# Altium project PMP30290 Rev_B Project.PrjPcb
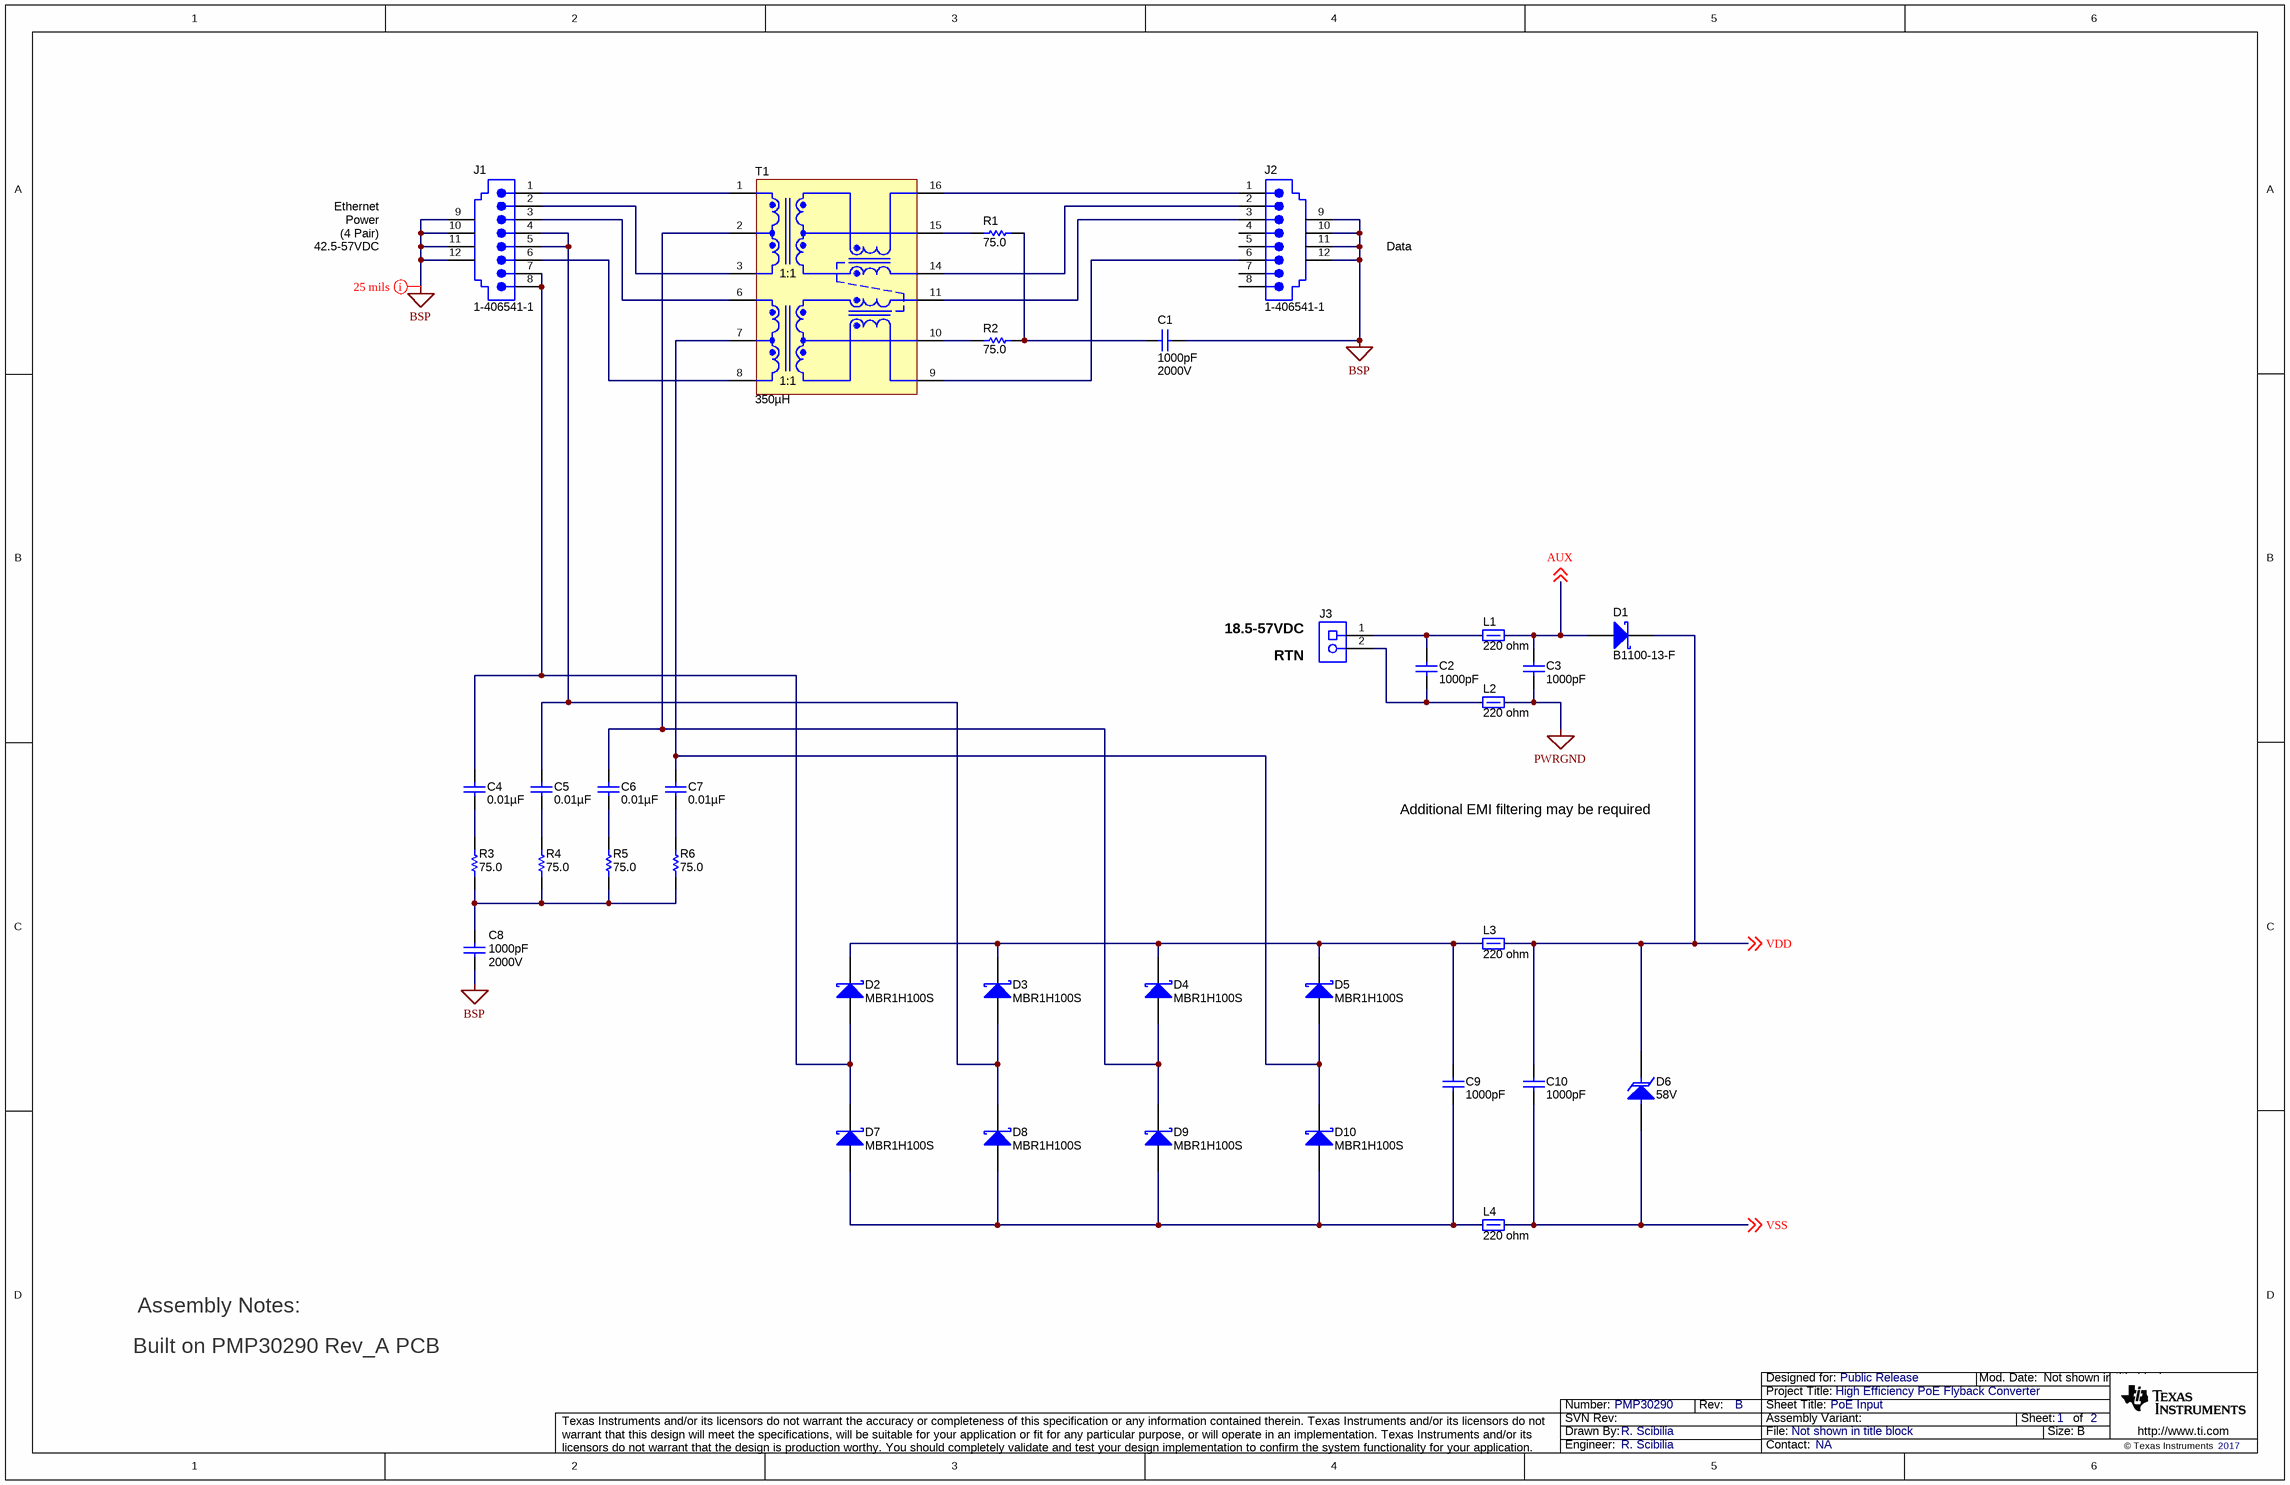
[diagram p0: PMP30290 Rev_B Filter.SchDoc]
CopyrightYear: 2017; PCB_Layout: R. Scibilia; PCB_Rev: A; PRJ_Customer: Public Release; PRJ_Engineer: R. Scibilia; PRJ_Number: PMP30290; PRJ_Title: High Efficiency PoE Flyback Converter; SCH_Rev: B; TechSupport: NA
2 sheets, 95 parts. Net scope: global (net labels, ports and power ports of the same name join across sheets).
Board file: PMP30290 Rev_A PCB.PcbDoc
Sheets:
  PMP30290 Rev_B Filter.SchDoc
  PMP30290 Rev_B Power Stage.SchDoc

## Sheet PMP30290 Rev_B Filter.SchDoc: PoE Input
size 431 x 279 mm; Date: Not shown in title block; ApprovedBy: Not shown in title block; CheckedBy: Not shown in title block; Author: Not shown in title block; CompanyName: Not shown in title block; DrawnBy: R. Scibilia; Engineer: Not shown in title block; Organization: Not shown in title block; Address1: Not shown in title block; Address2: Not shown in title block; Address3: Not shown in title block; Address4: Not shown in title block; DocumentNumber: 1; Revision: Use project parameter SCH_Rev; SheetNumber: 1; SheetTotal: 2; PageSetup: Record=PageOptions¦CenterHorizontal=True¦CenterVertical=True¦PrintScale=1.00¦XCorrection=1.00¦YCorrection=1.00¦PrintKind=0¦BorderSize=5000000¦LeftOffset=0¦BottomOffset=0¦Orientation=2¦PaperLength=1000¦PaperWidth=1000¦Scale=100¦PaperSource=15¦PrintQuality=600¦MediaType=1¦DitherType=10¦PaperKind=Letter¦PrintScaleMode=1

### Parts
C1  ValueDisplayed: 1000pF  Value2: 2000V  [1812_254]  (hidden comment: 1812GC102KA1)
C2  ValueDisplayed: 1000pF  [0603]  (hidden comment: C1608X7R2A102K080AA)
C3  ValueDisplayed: 1000pF  [0603]  (hidden comment: C1608X7R2A102K080AA)
C4  ValueDisplayed: 0.01µF  [0603]  (hidden comment: C0603C103K1RACTU)
C5  ValueDisplayed: 0.01µF  [0603]  (hidden comment: C0603C103K1RACTU)
C6  ValueDisplayed: 0.01µF  [0603]  (hidden comment: C0603C103K1RACTU)
C7  ValueDisplayed: 0.01µF  [0603]  (hidden comment: C0603C103K1RACTU)
C8  ValueDisplayed: 1000pF  Value2: 2000V  [1812_254]  (hidden comment: 1812GC102KA1)
C9  ValueDisplayed: 1000pF  [0603]  (hidden comment: C1608X7R2A102K080AA)
C10  ValueDisplayed: 1000pF  [0603]  (hidden comment: C1608X7R2A102K080AA)
D1  B1100-13-F  [SMA]
D2  value MBR1H100S  [SOD-123FL]  (hidden comment: MBR1H100SFT3G)
D3  value MBR1H100S  [SOD-123FL]  (hidden comment: MBR1H100SFT3G)
D4  value MBR1H100S  [SOD-123FL]  (hidden comment: MBR1H100SFT3G)
D5  value MBR1H100S  [SOD-123FL]  (hidden comment: MBR1H100SFT3G)
D6  value 58V  [SMA]  (hidden comment: SMAJ58A-13-F)
D7  value MBR1H100S  [SOD-123FL]  (hidden comment: MBR1H100SFT3G)
D8  value MBR1H100S  [SOD-123FL]  (hidden comment: MBR1H100SFT3G)
D9  value MBR1H100S  [SOD-123FL]  (hidden comment: MBR1H100SFT3G)
D10  value MBR1H100S  [SOD-123FL]  (hidden comment: MBR1H100SFT3G)
J1  1-406541-1  [TEC_1-406541-1]
J2  1-406541-1  [TEC_1-406541-1]
J3  ED555/2DS  [TERM_BLK_ED555-2DS]  (value not drawn)
L1  value 220 ohm  [0603]  (hidden comment: MPZ1608S221A)
L2  value 220 ohm  [0603]  (hidden comment: MPZ1608S221A)
L3  value 220 ohm  [0603]  (hidden comment: MPZ1608S221A)
L4  value 220 ohm  [0603]  (hidden comment: MPZ1608S221A)
R1  ValueDisplayed: 75.0  [0603L]  (hidden comment: CRCW060375R0FKEA)
R2  ValueDisplayed: 75.0  [0603L]  (hidden comment: CRCW060375R0FKEA)
R3  ValueDisplayed: 75.0  [0603L]  (hidden comment: CRCW060375R0FKEA)
R4  ValueDisplayed: 75.0  [0603L]  (hidden comment: CRCW060375R0FKEA)
R5  ValueDisplayed: 75.0  [0603L]  (hidden comment: CRCW060375R0FKEA)
R6  ValueDisplayed: 75.0  [0603L]  (hidden comment: CRCW060375R0FKEA)
T1  ValueDisplayed: 350µH  [PULSE_H2019FNL]  (hidden comment: H2019FNLT)

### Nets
BSP: C1.2 C8.2 J1.9 J1.10 J1.11 J1.12 J2.9 J2.10 J2.11 J2.12
PWRGND: C3.2 L2.2
AUX: C3.1 D1.2(A) L1.2 ; off-sheet AUX
VDD: C10.1 D1.1(K) D6.1(K) L3.2 ; off-sheet VDD
VSS: C10.2 D6.2(A) L4.2 ; off-sheet VSS
NetC1_1: C1.1 R1.1 R2.1
NetC2_1: C2.1 J3.1 L1.1
NetC2_2: C2.2 J3.2 L2.1
NetC4_1: C4.1 D2.2(A) D7.1(K) J1.7 J1.8
NetC4_2: C4.2 R3.2
NetC5_1: C5.1 D3.2(A) D8.1(K) J1.4 J1.5
NetC5_2: C5.2 R4.2
NetC6_1: C6.1 D4.2(A) D9.1(K) T1.2(TCT)
NetC6_2: C6.2 R5.2
NetC7_1: C7.1 D5.2(A) D10.1(K) T1.7(RCT)
NetC7_2: C7.2 R6.2
NetC8_1: C8.1 R3.1 R4.1 R5.1 R6.1
NetC9_1: C9.1 D2.1(K) D3.1(K) D4.1(K) D5.1(K) L3.1
NetC9_2: C9.2 D7.2(A) D8.2(A) D9.2(A) D10.2(A) L4.1
NetJ1_1: J1.1 T1.1(TD+)
NetJ1_2: J1.2 T1.3(TD-)
NetJ1_3: J1.3 T1.6(RD+)
NetJ1_6: J1.6 T1.8(RD-)
NetJ2_1: J2.1 T1.16(TX+)
NetJ2_2: J2.2 T1.14(TX-)
NetJ2_3: J2.3 T1.11(RX+)
NetJ2_6: J2.6 T1.9(RX-)
NetR1_2: R1.2 T1.15(TXCT)
NetR2_2: R2.2 T1.10(RXCT)

Not connected (* = marked no-connect by the designer): J2 4 5 7 8

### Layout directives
rule Clearance Constraint [Clearance = 20mil]: BSP

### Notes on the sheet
- Power
- Ethernet
- (4 Pair)
- 42.5-57VDC
- Data
- (near J3) 18.5-57VDC
- (near J3) RTN
- Additional EMI filtering may be required
- Assembly Notes:
- Built on PMP30290 Rev_A PCB

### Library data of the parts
C1 C8 = 1812GC102KA1: CAP, CERM, 1000 pF, 2000 V, +/- 10%, X7R, 1812; Manufacturer: AVX; Polarized: N; CompType: Capacitor; Value: 1000pF; U/M: EA; Cap_F: 0.000000001; Tolerance_%: 10; Value1: Unknown; VDC_V: 2000; TaMin_C: -55; TaMax_C: 125; Cap_Case: 1812; SizeArea_mm2: 14.4; SizeAreaWB_mm2: 23.1; SizeX_mm: 4.5; SizeY_mm: 3.2; SizeZ_mm: 2.54; AEC Category: Q200
C2 C3 C9 C10 = C1608X7R2A102K080AA: CAP, CERM, 1000 pF, 100 V, +/- 10%, X7R, 0603; Manufacturer: TDK; Polarized: N; CompType: Capacitor; Value: 1000pF; U/M: EA; Cap_F: 0.000000001; Tolerance_%: 10; Value1: Unknown; VDC_V: 100; Value2: 100V; TaMin_C: -55; TaMax_C: 125; SizeArea_mm2: 1.28; SizeAreaWB_mm2: 4.68; SizeX_mm: 1.6; SizeY_mm: 0.8; SizeZ_mm: 1; AEC Category: Q200; Green_Lifecycle: Active; Green_REACh: Passed
C4-C7 = C0603C103K1RACTU: CAP, CERM, 0.01 µF, 100 V, +/- 10%, X7R, 0603; Manufacturer: Kemet; Polarized: N; CompType: Capacitor; Value: 0.01uF; U/M: EA; Cap_F: 0.00000001; Tolerance_%: 10; Value1: Unknown; VDC_V: 100; Value2: 100V; TaMin_C: -55; TaMax_C: 125; SizeArea_mm2: 1.28; SizeAreaWB_mm2: 4.68; SizeX_mm: 1.6; SizeY_mm: 0.8; SizeZ_mm: 1; AEC Category: Q200; Green_Lifecycle: Active; Green_REACh: Passed
D1 = B1100-13-F: Diode, Schottky, 100 V, 1 A, SMA; Manufacturer: Diodes Inc.; Value: 100V; U/M: EA; Vf_V: 0.79; Value1: 1A; Value2: 0.79V; Io_A: 1; Vr_V: 100; TJmax_C: 150; RJC_CperW: 25; SizeAreaWB_mm2: 37.3428; SizeArea_mm2: 16.3228; SizeX_mm: 5.59; SizeY_mm: 2.92; SizeZ_mm: 2.87; AEC Category: Q101
D2-D5 D7-D10 = MBR1H100SFT3G: Diode, Schottky, 100 V, 1 A, SOD-123FL; Manufacturer: ON Semiconductor; U/M: EA; Vf_V: 0.76; Value1: 1A; Value2: 0.76V; Io_A: 1; Vr_V: 100; TJmax_C: 175; RJC_CperW: 85; SizeAreaWB_mm2: 12.19; SizeArea_mm2: 5.94; SizeX_mm: 3.6; SizeY_mm: 1.65; SizeZ_mm: 0.98; AEC Category: Q101; Green_Lifecycle: Active; Green_REACh: Passed
D6 = SMAJ58A-13-F: Diode, TVS, Uni, 58 V, SMA; Manufacturer: Diodes Inc.; U/M: EA; Power_W: 1; Vr_V: 58; Value1: 1W; SizeAreaWB_mm2: 37.3428; SizeArea_mm2: 16.3228; SizeX_mm: 5.59; SizeY_mm: 2.92; SizeZ_mm: 2.87; AEC Category: Q101
J1 J2 = 1-406541-1: RJ-45, Right Angle, No LED, tab up; Manufacturer: AMP; SymbolCreator: x0208326; Note: updated F/S per request.  Made footprint to max size.  2103-11-27; CompType: Connector; U/M: EA
J3 = ED555/2DS: Terminal Block, 3.5mm Pitch, 2x1, TH; Manufacturer: On-Shore Technology; SymbolCreator: a0412235; Pitch_mm: 3.5; Gender: Female; Shrouded: N; Row_Count: 1; ContactFinish: Brass; Current_A: 6; Voltage_V: 150; Cert_CULUS: Y; Green_Lifecycle: Active; Green_REACh: Passed
L1-L4 = MPZ1608S221A: Ferrite Bead, 220 ohm @ 100 MHz, 2.2 A, 0603; Manufacturer: TDK; Imax_A: 2.2; DCR_ohm: 0.05; Value1: 0.05 ohm; Value2: 2.2A; ZTyp@100MHz_Ohm: 220
R1-R6 = CRCW060375R0FKEA: RES, 75.0, 1%, 0.1 W, 0603; Manufacturer: Vishay-Dale; CompType: Resistor; Value: 75.0; Res_ohm: 75; Value_Code: 75R0; Tolerance_%: 1; Power_W: 0.1; Value2: 0.1W; TempCo: 100 ppm/C; EIA_Code: E96; U/M: EA; SizeArea_mm2: 1.28; SizeX_mm: 1.6; SizeY_mm: 0.8; AEC Category: Q200
T1 = H2019FNLT: Transformer, 350uH, SMT; Manufacturer: Pulse Engineering; SymbolCreator: x0208325; DCR_ohm: 0.65; Lp: 350; Ind_H: 0.00035; Green_Lifecycle: Not Set; Green_REACh: Incomplete

## Sheet PMP30290 Rev_B Power Stage.SchDoc: Flyback Converter
size 431 x 279 mm; Date: Not shown in title block; ApprovedBy: Not shown in title block; CheckedBy: Not shown in title block; Author: Not shown in title block; CompanyName: Not shown in title block; DrawnBy: R. Scibilia; Engineer: Not shown in title block; Organization: Not shown in title block; Address1: Not shown in title block; Address2: Not shown in title block; Address3: Not shown in title block; Address4: Not shown in title block; DocumentNumber: 2; Revision: Use project parameter SCH_Rev; SheetNumber: 2; SheetTotal: 2; PageSetup: Record=PageOptions¦CenterHorizontal=True¦CenterVertical=True¦PrintScale=0.66¦XCorrection=1.00¦YCorrection=1.00¦PrintKind=0¦BorderSize=5000000¦LeftOffset=0¦BottomOffset=0¦Orientation=2¦PaperLength=1000¦PaperWidth=1000¦Scale=100¦PaperSource=15¦PrintQuality=600¦MediaType=1¦DitherType=10¦PaperKind=Letter¦PrintScaleMode=1
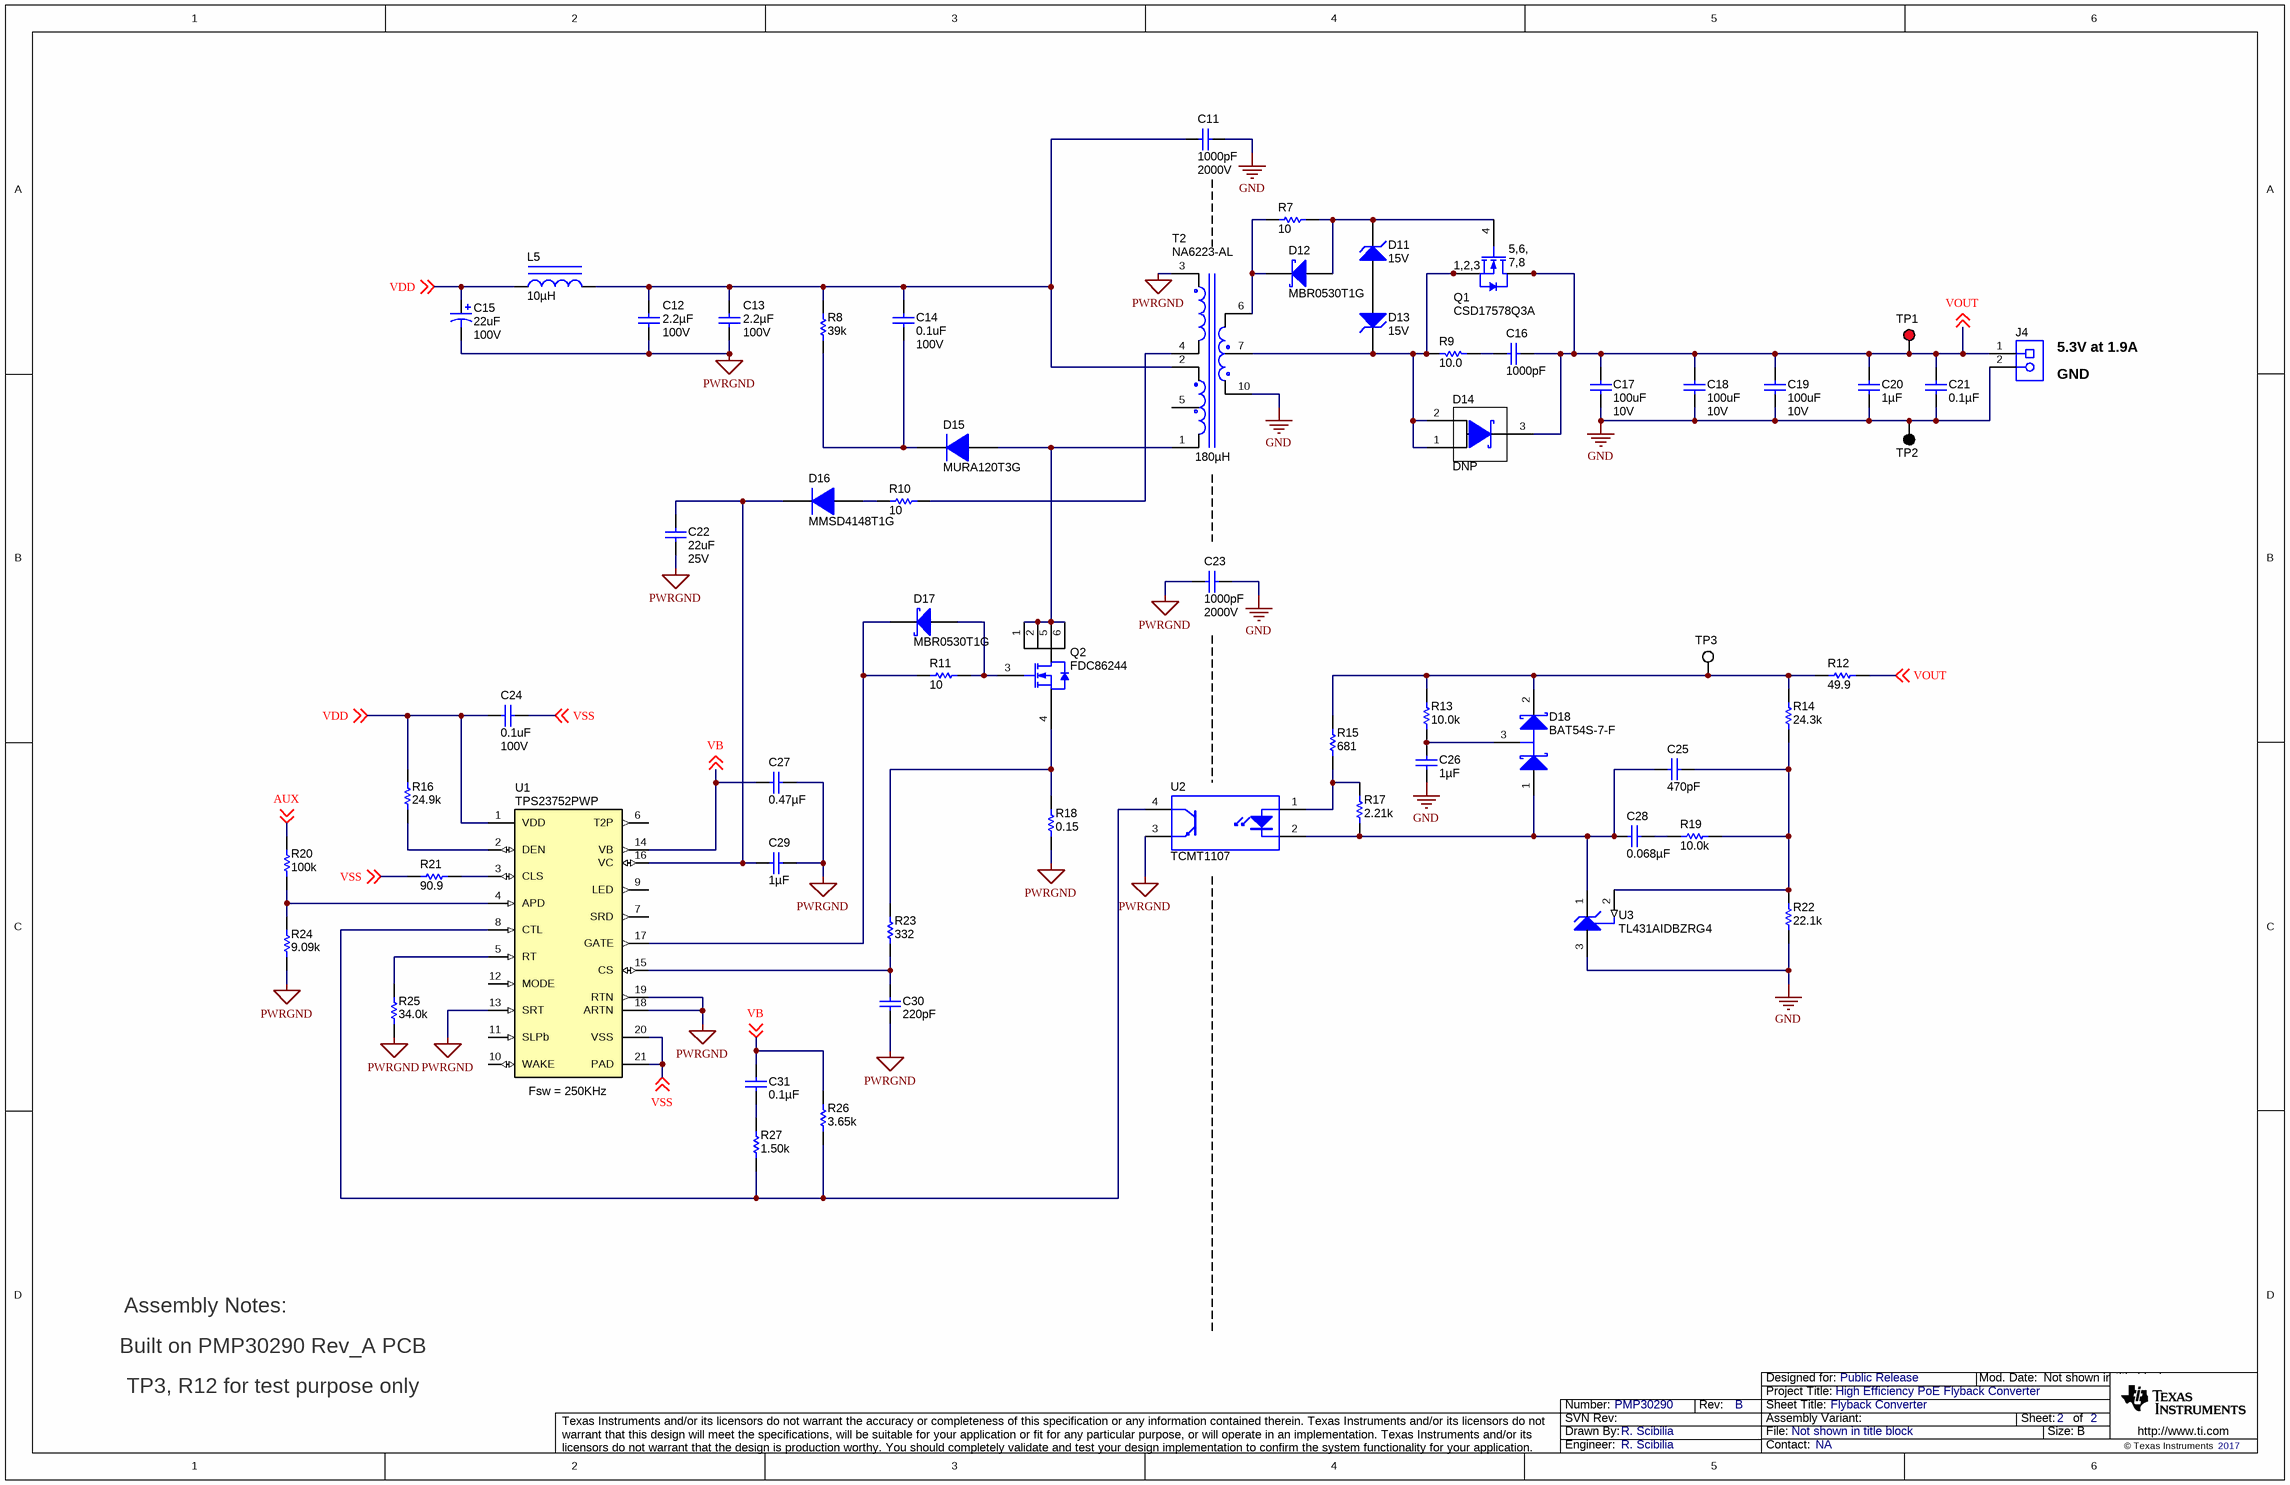
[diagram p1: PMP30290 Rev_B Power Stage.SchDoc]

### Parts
C11  ValueDisplayed: 1000pF  Value2: 2000V  [1812_254]  (hidden comment: 1812GC102KA1)
C12  ValueDisplayed: 2.2µF  Value2: 100V  [1210_270L]  (hidden comment: GRM32ER72A225KA35L)
C13  ValueDisplayed: 2.2µF  Value2: 100V  [1210_270L]  (hidden comment: GRM32ER72A225KA35L)
C14  value 0.1uF  Value2: 100V  [0805_HV]  (hidden comment: C2012X7R2A104K125AA)
C15  value 22uF  Value2: 100V  [CAPSMT_62_JA0]  (hidden comment: EMVH101ADA220MJA0G)
C16  ValueDisplayed: 1000pF  [0603]  (hidden comment: C1608X7R2A102K080AA)
C17  value 100uF  Value2: 10V  [1210_280]  (hidden comment: C1210C107M8PACTU)
C18  value 100uF  Value2: 10V  [1210_280]  (hidden comment: C1210C107M8PACTU)
C19  value 100uF  Value2: 10V  [1210_280]  (hidden comment: C1210C107M8PACTU)
C20  ValueDisplayed: 1µF  [0603]  (hidden comment: 885012206052)
C21  ValueDisplayed: 0.1µF  [0603]  (hidden comment: 885012206046)
C22  value 22uF  Value2: 25V  [1210_280]  (hidden comment: 12103D226MAT2A)
C23  ValueDisplayed: 1000pF  Value2: 2000V  [1812_254]  (hidden comment: 1812GC102KA1)
C24  value 0.1uF  Value2: 100V  [0805_HV]  (hidden comment: C2012X7R2A104K125AA)
C25  ValueDisplayed: 470pF  [0603]  (hidden comment: GRM1885C1H471JA01D)
C26  ValueDisplayed: 1µF  [0603]  (hidden comment: 885012206052)
C27  ValueDisplayed: 0.47µF  [0603]  (hidden comment: GRM188R71C474KA88D)
C28  ValueDisplayed: 0.068µF  [0603]  (hidden comment: GRM188R71H683KA93D)
C29  ValueDisplayed: 1µF  [0603]  (hidden comment: 885012206052)
C30  ValueDisplayed: 220pF  [0603]  (hidden comment: GRM1885C1H221JA01D)
C31  ValueDisplayed: 0.1µF  [0603]  (hidden comment: 885012206046)
D11  value 15V  [SOD-323]  (hidden comment: MMSZ5245BS-7-F)
D12  MBR0530T1G  [SOD-123]
D13  value 15V  [SOD-323]  (hidden comment: MMSZ5245BS-7-F)
D14  value DNP  [PowerDI5]  (hidden comment: PDS360-13)
D15  MURA120T3G  [SMA]
D16  MMSD4148T1G  [SOD-123]
D17  MBR0530T1G  [SOD-123]
D18  BAT54S-7-F  [SOT-23]
J4  ED555/2DS  [TERM_BLK_ED555-2DS]  (value not drawn)
L5  ValueDisplayed: 10µH  [LPS4018]  (hidden comment: LPS4018-103MRB)
Q1  CSD17578Q3A  [DNH0008A]
Q2  FDC86244  [SOT-6]
R7  value 10  [0805_HV]  (hidden comment: CRCW080510R0JNEA)
R8  value 39k  [0805_HV]  (hidden comment: CRCW080539K0JNEA)
R9  ValueDisplayed: 10.0  [2010]  (hidden comment: CRCW201010R0FKEF)
R10  value 10  [0805_HV]  (hidden comment: CRCW080510R0JNEA)
R11  value 10  [0805_HV]  (hidden comment: CRCW080510R0JNEA)
R12  ValueDisplayed: 49.9  [0603]  (hidden comment: RC0603FR-0749R9L)
R13  ValueDisplayed: 10.0k  [0603]  (hidden comment: RC0603FR-0710KL)
R14  ValueDisplayed: 24.3k  [0603]  (hidden comment: RC0603FR-0724K3L)
R15  ValueDisplayed: 681  [0603]  (hidden comment: RC0603FR-07681RL)
R16  ValueDisplayed: 24.9k  [0603]  (hidden comment: RC0603FR-0724K9L)
R17  ValueDisplayed: 2.21k  [0603]  (hidden comment: RC0603FR-072K21L)
R18  ValueDisplayed: 0.15  [1206]  (hidden comment: ERJ-8BSFR15V)
R19  ValueDisplayed: 10.0k  [0603]  (hidden comment: RC0603FR-0710KL)
R20  ValueDisplayed: 100k  [0603]  (hidden comment: RC0603FR-07100KL)
R21  ValueDisplayed: 90.9  [0603]  (hidden comment: RC0603FR-0790R9L)
R22  ValueDisplayed: 22.1k  [0603]  (hidden comment: RC0603FR-0722K1L)
R23  ValueDisplayed: 332  [0603]  (hidden comment: RC0603FR-07332RL)
R24  ValueDisplayed: 9.09k  [0603]  (hidden comment: RC0603FR-079K09L)
R25  ValueDisplayed: 34.0k  [0603]  (hidden comment: RC0603FR-0734KL)
R26  ValueDisplayed: 3.65k  [0603]  (hidden comment: RC0603FR-073K65L)
R27  ValueDisplayed: 1.50k  [0603]  (hidden comment: RC0603FR-071K5L)
T2  NA6223-AL  ValueDisplayed: 180µH  [XFMR_COILCRAFT-699x500x530]
TP1  5000  [Keystone5000]  (value not drawn)
TP2  5001  [Keystone5001]  (value not drawn)
TP3  5002  [Keystone5002]  (value not drawn)
U1  TPS23752PWP  [PWP0020D_N]
U2  TCMT1107  [SOP-4]
U3  TL431AIDBZRG4  [DBZ0003A_N]

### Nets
GND: C11.2 C17.2 C18.2 C19.2 C20.2 C21.2 C23.2 C26.2 J4.2 R22.1 T2.10 TP2.1 U3.3(ANODE)
PWRGND: C12.2 C13.2 C15.2(-) C22.2 C23.1 C27.1 C29.2 C30.2 R18.1 R24.1 R25.1 T2.3 U1.13(SRT) U1.18(ARTN) U1.19(RTN) U2.3(E)
AUX: R20.2 ; off-sheet AUX
VB: C27.2 C31.1 R26.2 U1.14(VB) ; off-sheet VB
VDD: C15.1(+) C24.1 L5.1 R16.2 U1.1(VDD) ; off-sheet VDD
VOUT: C16.2 C17.1 C18.1 C19.1 C20.1 C21.1 D14.3(K) J4.1 Q1.5(D) Q1.6(D) Q1.7(D) Q1.8(D) Q1.9(D) R12.2 TP1.1 ; off-sheet VOUT
VSS: C24.2 R21.1 U1.20(VSS) U1.21(PAD) ; off-sheet VSS
NetC11_1: C11.1 C12.1 C13.1 C14.1 L5.2 R8.2 T2.2
NetC14_2: C14.2 D15.1(K) R8.1
NetC16_1: C16.1 R9.2
NetC22_1: C22.1 C29.1 D16.1(K) U1.16(VC)
NetC25_1: C25.1 R14.1 R19.1 R22.2 U3.2(REF)
NetC25_2: C25.2 C28.2 D18.1(A) R17.1 U2.2(K) U3.1(CATHODE)
NetC26_1: C26.1 D18.3(C) R13.1
NetC28_1: C28.1 R19.2
NetC30_1: C30.1 R23.1 U1.15(CS)
NetC31_2: C31.2 R27.2
NetD11_1: D11.1(K) D12.2(A) Q1.4(G) R7.2
NetD11_2: D11.2(A) D13.2(A)
NetD12_1: D12.1(K) R7.1 T2.6
NetD13_1: D13.1(K) D14.1(A) D14.2(A) Q1.1(S) Q1.2(S) Q1.3(S) R9.1 T2.7
NetD15_2: D15.2(A) Q2.1(D) Q2.2(D) Q2.5(D) Q2.6(D) T2.1
NetD16_2: D16.2(A) R10.1
NetD17_1: D17.1(K) R11.1 U1.17(GATE)
NetD17_2: D17.2(A) Q2.3(G) R11.2
NetD18_2: D18.2(K) R12.1 R13.2 R14.2 R15.2 TP3.1
NetQ2_4: Q2.4(S) R18.2 R23.2
NetR10_2: R10.2 T2.4
NetR15_1: R15.1 R17.2 U2.1(A)
NetR16_1: R16.1 U1.2(DEN)
NetR20_1: R20.1 R24.2 U1.4(APD)
NetR21_2: R21.2 U1.3(CLS)
NetR25_2: R25.2 U1.5(RT)
NetR26_1: R26.1 R27.1 U1.8(CTL) U2.4(C)

Not connected (* = marked no-connect by the designer): T2 5; U1 6(T2P) 7(SRD) 9(LED) 10(WAKE) 11(SLPb) 12(MODE)

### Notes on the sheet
- (near J4) 5.3V at 1.9A
- (near J4) GND
- (near U1) Fsw = 250KHz
- Assembly Notes:
- Built on PMP30290 Rev_A PCB
- TP3, R12 for test purpose only

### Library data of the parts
C11 C23 = 1812GC102KA1: as C1 on sheet PMP30290 Rev_B Filter
C12 C13 = GRM32ER72A225KA35L: CAP, CERM, 2.2 µF, 100 V, +/- 10%, X7R, 1210; Manufacturer: MuRata; Polarized: N; CompType: Capacitor; Value: 2.2uF; U/M: EA; Cap_F: 0.0000022; Tolerance_%: 10; ESR_ohm: 0.007; Value1: 0.007 ohm; VDC_V: 100; IRMS_A: 4.4; TaMin_C: -55; TaMax_C: 125; Cap_Case: 1210; SizeArea_mm2: 8; SizeAreaWB_mm2: 14.7; SizeX_mm: 3.2; SizeY_mm: 2.5; SizeZ_mm: 2.7; AEC Category: Q200
C14 C24 = C2012X7R2A104K125AA: CAP, CERM, 0.1 µF, 100 V, +/- 10%, X7R, 0805; Manufacturer: TDK; Polarized: N; CompType: Capacitor; ValueDisplayed: 0.1µF; U/M: EA; Cap_F: 0.0000001; Tolerance_%: 10; ESR_ohm: 0.020726; Value1: 0.020726 ohm; VDC_V: 100; IRMS_A: 1.456; TaMin_C: -55; TaMax_C: 125; Cap_Case: 0805; SizeArea_mm2: 2.5; SizeAreaWB_mm2: 6.75; SizeX_mm: 2; SizeY_mm: 1.25; SizeZ_mm: 1.45; AEC Category: Q200; Green_Lifecycle: Active; Green_REACh: Passed
C15 = EMVH101ADA220MJA0G: CAP, AL, 22 µF, 100 V, +/- 20%, 0.55 ohm, SMD; Manufacturer: Chemi-Con; Polarized: Y; CompType: Capacitor; ValueDisplayed: 22µF; U/M: EA; Cap_F: 0.000022; Tolerance_%: 20; VDC_V: 100; ESR_ohm: 0.55; IRMS_A: 0.115; TaMin_C: -40; TaMax_C: 125; Cap_Case: JA0; SizeAreaWB_mm2: 151.29; SizeArea_mm2: 106.09; SizeX_mm: 10.3; SizeZ_mm: 10; AEC Category: Q200; Green_Lifecycle: Active; Green_REACh: Passed
C16 = C1608X7R2A102K080AA: as C2 on sheet PMP30290 Rev_B Filter
C17-C19 = C1210C107M8PACTU: CAP, CERM, 100 µF, 10 V, +/- 20%, X5R, 1210; Manufacturer: Wurth Elektronik; Polarized: N; CompType: Capacitor; ValueDisplayed: 100µF; U/M: EA; Cap_F: 0.0001; Tolerance_%: 20; Value1: Unknown; VDC_V: 10; TaMin_C: -55; TaMax_C: 85; Cap_Case: 1210; SizeArea_mm2: 8; SizeAreaWB_mm2: 14.7; SizeX_mm: 3.2; SizeY_mm: 2.5; SizeZ_mm: 2.8; AEC Category: Q200; Green_Lifecycle: Active; Green_REACh: Passed
C20 C26 C29 = 885012206052: CAP, CERM, 1 µF, 16 V, +/- 10%, X7R, 0603; Manufacturer: Wurth Elektronik; Polarized: N; CompType: Capacitor; Value: 1uF; U/M: EA; Cap_F: 0.000001; Tolerance_%: 10; Value1: Unknown; VDC_V: 16; Value2: 16V; TaMin_C: -55; TaMax_C: 125; SizeArea_mm2: 1.28; SizeAreaWB_mm2: 4.68; SizeX_mm: 1.6; SizeY_mm: 0.8; SizeZ_mm: 1; AEC Category: Q200; Green_Lifecycle: Active; Green_REACh: Passed
C21 C31 = 885012206046: CAP, CERM, 0.1 µF, 16 V, +/- 10%, X7R, 0603; Manufacturer: Wurth Elektronik; Polarized: N; CompType: Capacitor; Value: 0.1uF; U/M: EA; Cap_F: 0.0000001; Tolerance_%: 10; Value1: Unknown; VDC_V: 16; Value2: 16V; TaMin_C: -55; TaMax_C: 125; SizeArea_mm2: 1.28; SizeAreaWB_mm2: 4.68; SizeX_mm: 1.6; SizeY_mm: 0.8; SizeZ_mm: 1; AEC Category: Q200
C22 = 12103D226MAT2A: CAP, CERM, 22 µF, 25 V, +/- 20%, X5R, 1210; Manufacturer: AVX; Polarized: N; CompType: Capacitor; ValueDisplayed: 22µF; U/M: EA; Cap_F: 0.000022; Tolerance_%: 20; Value1: Unknown; VDC_V: 25; TaMin_C: -55; TaMax_C: 85; Cap_Case: 1210; SizeArea_mm2: 8; SizeAreaWB_mm2: 14.7; SizeX_mm: 3.2; SizeY_mm: 2.5; SizeZ_mm: 2.8; AEC Category: Q200; Green_Lifecycle: Active; Green_REACh: Passed
C25 = GRM1885C1H471JA01D: CAP, CERM, 470 pF, 50 V, +/- 5%, C0G/NP0, 0603; Manufacturer: MuRata; Polarized: N; CompType: Capacitor; Value: 470pF; U/M: EA; Cap_F: 0.00000000047; Tolerance_%: 5; Value1: Unknown; VDC_V: 50; Value2: 50V; TaMin_C: -55; TaMax_C: 125; SizeArea_mm2: 1.28; SizeAreaWB_mm2: 4.68; SizeX_mm: 1.6; SizeY_mm: 0.8; SizeZ_mm: 1; AEC Category: Q200; Green_Lifecycle: Active; Green_REACh: Passed
C27 = GRM188R71C474KA88D: CAP, CERM, 0.47 µF, 16 V, +/- 10%, X7R, 0603; Manufacturer: MuRata; Polarized: N; CompType: Capacitor; Value: 0.47uF; U/M: EA; Cap_F: 0.00000047; Tolerance_%: 10; Value1: Unknown; VDC_V: 16; Value2: 16V; TaMin_C: -55; TaMax_C: 125; SizeArea_mm2: 1.28; SizeAreaWB_mm2: 4.68; SizeX_mm: 1.6; SizeY_mm: 0.8; SizeZ_mm: 1; AEC Category: Q200
C28 = GRM188R71H683KA93D: CAP, CERM, 0.068 µF, 50 V, +/- 10%, X7R, 0603; Manufacturer: MuRata; Polarized: N; CompType: Capacitor; Value: 0.068uF; U/M: EA; Cap_F: 0.000000068; Tolerance_%: 10; Value1: Unknown; VDC_V: 50; Value2: 50V; TaMin_C: -55; TaMax_C: 125; SizeArea_mm2: 1.28; SizeAreaWB_mm2: 4.68; SizeX_mm: 1.6; SizeY_mm: 0.8; SizeZ_mm: 1; AEC Category: Q200; Green_Lifecycle: Active; Green_REACh: Passed
C30 = GRM1885C1H221JA01D: CAP, CERM, 220 pF, 50 V, +/- 5%, C0G/NP0, 0603; Manufacturer: MuRata; Polarized: N; CompType: Capacitor; Value: 220pF; U/M: EA; Cap_F: 0.00000000022; Tolerance_%: 5; Value1: Unknown; VDC_V: 50; Value2: 50V; TaMin_C: -55; TaMax_C: 125; SizeArea_mm2: 1.28; SizeAreaWB_mm2: 4.68; SizeX_mm: 1.6; SizeY_mm: 0.8; SizeZ_mm: 1; AEC Category: Q200; Green_Lifecycle: Active; Green_REACh: Passed
D11 D13 = MMSZ5245BS-7-F: Diode, Zener, 15 V, 200 mW, SOD-323; Manufacturer: Diodes Inc.; SymbolCreator: a0412235; U/M: EA; Power_W: 0.2; Vz_V: 15; Value1: 0.2W; RJA_CperW: 350; SizeAreaWB_mm2: 8.695; SizeArea_mm2: 3.645; SizeX_mm: 2.7; SizeY_mm: 1.35; SizeZ_mm: 1; AEC Category: Q101
D12 D17 = MBR0530T1G: Diode, Schottky, 30 V, 0.5 A, SOD-123; Manufacturer: ON Semiconductor; U/M: EA; Vf_V: 0.43; Value1: 0.5A; Value2: 0.43V; Io_A: 0.5; Vr_V: 30; TJmax_C: 125; RJC_CperW: 150; SizeAreaWB_mm2: 13.095; SizeArea_mm2: 6.545; SizeX_mm: 3.85; SizeY_mm: 1.7; SizeZ_mm: 1.35; AEC Category: Q101; Green_Lifecycle: Active; Green_REACh: Passed
D14 = PDS360-13: Diode, Schottky, 60 V, 3 A, PowerDI5; Manufacturer: Diodes Inc.; U/M: EA; Vf_V: 0.62; Value1: 3A; Value2: 0.62V; Io_A: 3; Vr_V: 60; TJmax_C: 150; SizeAreaWB_mm2: 49.56; SizeArea_mm2: 24.96; SizeX_mm: 6.4; SizeY_mm: 3.9; SizeZ_mm: 1.05; AEC Category: Q101
D15 = MURA120T3G: Diode, Ultrafast, 200 V, 1 A, SMA; Manufacturer: ON Semiconductor; U/M: EA; Vf_V: 0.0875; Value1: 1A; Value2: 0.0875V; Io_A: 1; Vr_V: 200; TJmax_C: 175; SizeAreaWB_mm2: 37.3428; SizeArea_mm2: 16.3228; SizeX_mm: 5.59; SizeY_mm: 2.92; SizeZ_mm: 2.87; AEC Category: Q101; Green_Lifecycle: Active; Green_REACh: Passed
D16 = MMSD4148T1G: Diode, Switching, 100 V, 0.2 A, SOD-123; Manufacturer: ON Semiconductor; U/M: EA; Vf_V: 1; Value1: 0.2A; Value2: 1V; Io_A: 0.2; Vr_V: 100; TJmax_C: 150; SizeAreaWB_mm2: 13.095; SizeArea_mm2: 6.545; SizeX_mm: 3.85; SizeY_mm: 1.7; SizeZ_mm: 1.35; AEC Category: Q101
D18 = BAT54S-7-F: Diode, Schottky, 30 V, 0.2 A, SOT-23; Manufacturer: Diodes Inc.; U/M: EA; Vf_V: 0.65; Value1: 0.2A; Value2: 0.65V; Io_A: 0.2; Vr_V: 30; TJmax_C: 125; SizeAreaWB_mm2: 14; SizeArea_mm2: 7.5; SizeX_mm: 2.5; SizeY_mm: 3; SizeZ_mm: 1.1; AEC Category: Q101
J4 = ED555/2DS: as J3 on sheet PMP30290 Rev_B Filter
L5 = LPS4018-103MRB: Inductor, Shielded Drum Core, Ferrite, 10 µH, 1.25 A, 0.18 ohm, SMD; Manufacturer: Coilcraft; Value: 10uH; Ind_H: 10.0E-6; Imax_A: 1.25; Irms: 1.25A @ 40C rise; Isat: 1.3A @ 30% inductance drop; DCR_ohm: 0.18; Value2: 1.25A; SizeAreaWB_mm2: 24.01; SizeArea_mm2: 15.21; SizeX_mm: 3.9; SizeZ_mm: 1.7; AEC Category: Q200; AEC Qualified: N; Green_Lifecycle: Not Set; Green_REACh: Incomplete
Q1 = CSD17578Q3A: MOSFET, N-CH, 30 V, 14 A, DNH0008A (VSONP-8); Manufacturer: Texas Instruments; Alternate Manufacturer: None; U/M: EA; ChType: N; Value: 30V; VdsMax_V: 30; Value1: 0.0082 ohm; Rdson45_ohm: 0.0082; Value2: 7.9 nC; QgTyp_nC: 7.9; Vgs_V: 20; IdsMax_A: 14; SizeAreaWB_mm2: 18.49; SizeArea_mm2: 10.89; SizeX_mm: 3.3; SizeZ_mm: 0.9; AEC Category: Q101
Q2 = FDC86244: MOSFET, N-CH, 150 V, 2.3 A, SuperSOT-6; Manufacturer: Fairchild Semiconductor; Alternate Manufacturer: None; SymbolCreator: x0208325; U/M: EA; ChType: N; VdsMax_V: 150; Value1: ? ohm; Value2: 4.2 nC; QgTyp_nC: 4.2; Vgs_V: 20; IdsMax_A: 2.3; SizeAreaWB_mm2: 14.82; SizeArea_mm2: 8.12; SizeX_mm: 2.9; SizeY_mm: 2.8; SizeZ_mm: 1.1; AEC Category: Q101; Green_Lifecycle: Active; Green_REACh: Passed
R7 R10 R11 = CRCW080510R0JNEA: RES, 10, 5%, 0.125 W, 0805; Manufacturer: Vishay-Dale; CompType: Resistor; Value_Code: 10R0; Tolerance_%: 5; Power_W: 0.125; Value2: 0.125W; VDC_V: 150; TempCo: 200 ppm/C; EIA_Code: E24; U/M: EA; SizeArea_mm2: 2.5; SizeX_mm: 2; SizeY_mm: 1.25; SizeZ_mm: 1.45; AEC Category: Q200
R8 = CRCW080539K0JNEA: RES, 39 k, 5%, 0.125 W, 0805; Manufacturer: Vishay-Dale; CompType: Resistor; Res_ohm: 39000; Value_Code: 39k0; Tolerance_%: 5; Power_W: 0.125; Value2: 0.125W; VDC_V: 150; TempCo: 200 ppm/C; EIA_Code: E24; U/M: EA; SizeArea_mm2: 2.5; SizeX_mm: 2; SizeY_mm: 1.25; SizeZ_mm: 1.45; AEC Category: Q200
R9 = CRCW201010R0FKEF: RES, 10.0, 1%, 0.75 W, AEC-Q200 Grade 0, 2010; Manufacturer: Vishay-Dale; CompType: Resistor; Value: 10.0; Res_ohm: 10; Value_Code: 10R0; Tolerance_%: 1; Power_W: 0.75; Value2: 0.75W; VDC_V: 400; TempCo: 100 ppm/C; SizeArea_mm2: 12.5; SizeX_mm: 5; SizeY_mm: 2.5; SizeZ_mm: 1.66; EIA_Code: E96; U/M: EA; AEC Category: Q200; AEC Qualified: Y; AEC Grade: 0
R12 = RC0603FR-0749R9L: RES, 49.9, 1%, 0.1 W, 0603; Manufacturer: Yageo America; CompType: Resistor; Value: 49.9; Value_Code: 49R9; Tolerance_%: 1; Power_W: 0.1; Value2: 0.1W; VDC_V: 150; TempCo: 200 ppm/C; SizeArea_mm2: 1.28; SizeX_mm: 1.6; SizeY_mm: 0.8; EIA_Code: E96; U/M: EA; AEC Category: Q200; Green_Lifecycle: Active; Green_REACh: Passed
R13 R19 = RC0603FR-0710KL: RES, 10.0 k, 1%, 0.1 W, 0603; Manufacturer: Yageo America; CompType: Resistor; Value: 10.0k; Res_ohm: 10000; Value_Code: 10k0; Tolerance_%: 1; Power_W: 0.1; Value2: 0.1W; VDC_V: 150; TempCo: 200 ppm/C; SizeArea_mm2: 1.28; SizeX_mm: 1.6; SizeY_mm: 0.8; EIA_Code: E96; U/M: EA; AEC Category: Q200; Green_Lifecycle: Active; Green_REACh: Passed
R14 = RC0603FR-0724K3L: RES, 24.3 k, 1%, 0.1 W, 0603; Manufacturer: Yageo America; CompType: Resistor; Value: 24.3k; Res_ohm: 24300; Value_Code: 24k3; Tolerance_%: 1; Power_W: 0.1; Value2: 0.1W; VDC_V: 150; TempCo: 200 ppm/C; SizeArea_mm2: 1.28; SizeX_mm: 1.6; SizeY_mm: 0.8; EIA_Code: E96; U/M: EA; AEC Category: Q200
R15 = RC0603FR-07681RL: RES, 681, 1%, 0.1 W, 0603; Manufacturer: Yageo America; CompType: Resistor; Value: 681; Value_Code: 681R; Tolerance_%: 1; Power_W: 0.1; Value2: 0.1W; VDC_V: 150; TempCo: 200 ppm/C; SizeArea_mm2: 1.28; SizeX_mm: 1.6; SizeY_mm: 0.8; EIA_Code: E96; U/M: EA; AEC Category: Q200
R16 = RC0603FR-0724K9L: RES, 24.9 k, 1%, 0.1 W, 0603; Manufacturer: Yageo America; CompType: Resistor; Value: 24.9k; Res_ohm: 24900; Value_Code: 24k9; Tolerance_%: 1; Power_W: 0.1; Value2: 0.1W; VDC_V: 150; TempCo: 200 ppm/C; SizeArea_mm2: 1.28; SizeX_mm: 1.6; SizeY_mm: 0.8; EIA_Code: E96; U/M: EA; AEC Category: Q200; Green_Lifecycle: Active; Green_REACh: Passed
R17 = RC0603FR-072K21L: RES, 2.21 k, 1%, 0.1 W, 0603; Manufacturer: Yageo America; CompType: Resistor; Value: 2.21k; Res_ohm: 2210; Value_Code: 2k21; Tolerance_%: 1; Power_W: 0.1; Value2: 0.1W; VDC_V: 150; TempCo: 200 ppm/C; SizeArea_mm2: 1.28; SizeX_mm: 1.6; SizeY_mm: 0.8; EIA_Code: E96; U/M: EA; AEC Category: Q200; Green_Lifecycle: Active; Green_REACh: Passed
R18 = ERJ-8BSFR15V: RES, 0.15, 1%, 0.5 W, 1206; Manufacturer: Panasonic; CompType: Resistor; Value: 0.15; Value_Code: R150; Tolerance_%: 1; Power_W: 0.5; Value2: 0.5W; TempCo: 250 ppm/C; SizeArea_mm2: 5.12; SizeX_mm: 3.2; SizeY_mm: 1.6; SizeZ_mm: 1.35; EIA_Code: E96; U/M: EA; AEC Category: Q200; AEC Qualified: N
R20 = RC0603FR-07100KL: RES, 100 k, 1%, 0.1 W, 0603; Manufacturer: Yageo America; CompType: Resistor; Value: 100k; Res_ohm: 100000; Tolerance_%: 1; Power_W: 0.1; Value2: 0.1W; VDC_V: 150; TempCo: 200 ppm/C; SizeArea_mm2: 1.28; SizeX_mm: 1.6; SizeY_mm: 0.8; EIA_Code: E96; U/M: EA; AEC Category: Q200; Green_Lifecycle: Active; Green_REACh: Passed
R21 = RC0603FR-0790R9L: RES, 90.9, 1%, 0.1 W, 0603; Manufacturer: Yageo America; CompType: Resistor; Value: 90.9; Value_Code: 90R9; Tolerance_%: 1; Power_W: 0.1; Value2: 0.1W; VDC_V: 150; TempCo: 200 ppm/C; SizeArea_mm2: 1.28; SizeX_mm: 1.6; SizeY_mm: 0.8; EIA_Code: E96; U/M: EA; AEC Category: Q200
R22 = RC0603FR-0722K1L: RES, 22.1 k, 1%, 0.1 W, 0603; Manufacturer: Yageo America; CompType: Resistor; Value: 22.1k; Res_ohm: 22100; Value_Code: 22k1; Tolerance_%: 1; Power_W: 0.1; Value2: 0.1W; VDC_V: 150; TempCo: 200 ppm/C; SizeArea_mm2: 1.28; SizeX_mm: 1.6; SizeY_mm: 0.8; EIA_Code: E96; U/M: EA; AEC Category: Q200; Green_Lifecycle: Active; Green_REACh: Passed
R23 = RC0603FR-07332RL: RES, 332, 1%, 0.1 W, 0603; Manufacturer: Yageo America; CompType: Resistor; Value: 332; Value_Code: 332R; Tolerance_%: 1; Power_W: 0.1; Value2: 0.1W; VDC_V: 150; TempCo: 200 ppm/C; SizeArea_mm2: 1.28; SizeX_mm: 1.6; SizeY_mm: 0.8; EIA_Code: E96; U/M: EA; AEC Category: Q200; Green_Lifecycle: Active; Green_REACh: Passed
R24 = RC0603FR-079K09L: RES, 9.09 k, 1%, 0.1 W, 0603; Manufacturer: Yageo America; CompType: Resistor; Value: 9.09k; Res_ohm: 9090; Value_Code: 9k09; Tolerance_%: 1; Power_W: 0.1; Value2: 0.1W; VDC_V: 150; TempCo: 200 ppm/C; SizeArea_mm2: 1.28; SizeX_mm: 1.6; SizeY_mm: 0.8; EIA_Code: E96; U/M: EA; AEC Category: Q200; Green_Lifecycle: Active; Green_REACh: Passed
R25 = RC0603FR-0734KL: RES, 34.0 k, 1%, 0.1 W, 0603; Manufacturer: Yageo America; CompType: Resistor; Value: 34.0k; Res_ohm: 34000; Value_Code: 34k0; Tolerance_%: 1; Power_W: 0.1; Value2: 0.1W; VDC_V: 150; TempCo: 200 ppm/C; SizeArea_mm2: 1.28; SizeX_mm: 1.6; SizeY_mm: 0.8; EIA_Code: E96; U/M: EA; AEC Category: Q200
R26 = RC0603FR-073K65L: RES, 3.65 k, 1%, 0.1 W, 0603; Manufacturer: Yageo America; CompType: Resistor; Value: 3.65k; Res_ohm: 3650; Value_Code: 3k65; Tolerance_%: 1; Power_W: 0.1; Value2: 0.1W; VDC_V: 150; TempCo: 200 ppm/C; SizeArea_mm2: 1.28; SizeX_mm: 1.6; SizeY_mm: 0.8; EIA_Code: E96; U/M: EA; AEC Category: Q200; Green_Lifecycle: Active; Green_REACh: Passed
R27 = RC0603FR-071K5L: RES, 1.50 k, 1%, 0.1 W, 0603; Manufacturer: Yageo America; CompType: Resistor; Value: 1.50k; Res_ohm: 1500; Value_Code: 1k50; Tolerance_%: 1; Power_W: 0.1; Value2: 0.1W; VDC_V: 150; TempCo: 200 ppm/C; SizeArea_mm2: 1.28; SizeX_mm: 1.6; SizeY_mm: 0.8; EIA_Code: E96; U/M: EA; AEC Category: Q200; Green_Lifecycle: Active; Green_REACh: Passed
T2 = NA6223-AL: Transformer, Flyback, 198 uH; Manufacturer: Coilcraft; SymbolCreator: a0799628; Value: 198uH; DCR_ohm: 0.23; Lp: 198; Ind_H: 0.000198; Green_Lifecycle: Not Set; Green_REACh: Incomplete
TP1 = 5000: Test Point, Miniature, Red, TH; Manufacturer: Keystone; CompType: Test Point Loop; ContactFinish: Silver; Green_Lifecycle: Active; Green_REACh: Passed
TP2 = 5001: Test Point, Miniature, Black, TH; Manufacturer: Keystone; CompType: Test Point Loop; ContactFinish: Silver; Green_Lifecycle: Active; Green_REACh: Passed
TP3 = 5002: Test Point, Miniature, White, TH; Manufacturer: Keystone; CompType: Test Point Loop; ContactFinish: Silver; Green_Lifecycle: Active; Green_REACh: Passed
U1 = TPS23752PWP: IEEE 802.3at PoE Interface and Green-mode DC/DC Controller, PWP0020D (TSSOP-20); Manufacturer: Texas Instruments; SymbolCreator: x0208326; SizeArea_mm2: 41.6; SizeAreaWB_mm2: 71.4; SizeX_mm: 6.4; SizeY_mm: 6.5; SizeZ_mm: 1.2; CompType: IC; U/M: EA; Green_Lifecycle: Active; Green_REACh: Passed
U2 = TCMT1107: Optocoupler, 3.75 kV, 80-160% CTR, SMT; Manufacturer: Vishay-Semiconductor; CTR (Min): 80%; CTR (Max): 160%; Voltage_Isolation_Vrms: 3750V; SizeAreaWB_mm2: 43.65; SizeArea_mm2: 19.95; SizeX_mm: 7; SizeY_mm: 2.85; SizeZ_mm: 2.3
U3 = TL431AIDBZRG4: Adjustable Precision Shunt Regulator, 34 ppm / degC, 100 mA, -40 to 85 degC, 3-pin SOT-23 (DBZ), Green (RoHS & no Sb/Br); Manufacturer: Texas Instruments; Alternate PartNumber: Equivalent; Initial Accuracy @ 25/deg C(%): 1; Iout/Iz(Max)(mA): 100; Min Iz for Regulation(uA): 600; Rating: Catalog; SubFamily: Shunt Voltage Reference; Temp Coeff(Max)(ppm/ degree C): 92; Temp Coeff(Typ)(ppm/ degree C): 34; VO Adj(Max)(V): 36; VO Adj(Min)(V): 2.495

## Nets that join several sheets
PWRGND: PMP30290 Rev_B Filter (C3.2 L2.2), PMP30290 Rev_B Power Stage (16 pins)
AUX: PMP30290 Rev_B Filter (C3.1 D1.2 L1.2), PMP30290 Rev_B Power Stage (R20.2)
VDD: PMP30290 Rev_B Filter (C10.1 D1.1 D6.1 L3.2), PMP30290 Rev_B Power Stage (5 pins)
VSS: PMP30290 Rev_B Filter (C10.2 D6.2 L4.2), PMP30290 Rev_B Power Stage (C24.2 R21.1 U1.20 U1.21)

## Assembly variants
001: not fitted FID1 FID2 FID3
